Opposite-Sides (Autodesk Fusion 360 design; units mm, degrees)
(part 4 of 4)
extrude "Extrude2" cut sketch "Underside M3 insert" along normal blind 6.9
work_plane "WorkPlane3" AlongDistance 2.9 ExtraOffset 0
sketch "Underside M3 insert (1)" plane through (0, 0, 2.9) normal (0, 0, 1) x axis (1, 0, 0)
  circle C1 centre (-29, -55) radius 2
extrude "Extrude3" cut sketch "Underside M3 insert (1)" along normal blind 6.9
work_plane "WorkPlane4" AlongDistance 2.9 ExtraOffset 0
sketch "Underside M3 insert (2)" plane through (0, 0, 2.9) normal (0, 0, 1) x axis (1, 0, 0)
  circle C1 centre (-37, -55) radius 2
extrude "Extrude4" cut sketch "Underside M3 insert (2)" along normal blind 6.9
work_plane "WorkPlane5" AlongDistance 9.7 ExtraOffset 0
sketch "Preload screw passage" plane through (0, 0, 9.7) normal (0, 0, 1) x axis (1, 0, 0)
  circle C1 centre (-37, -55) radius 1.7
extrude "Extrude5" cut sketch "Preload screw passage" along normal blind 14.4
work_plane "WorkPlane6" AlongDistance 20 ExtraOffset 0
sketch "Preload collar recess" plane through (0, 0, 20) normal (0, 0, 1) x axis (1, 0, 0)
  circle C1 centre (-37, -55) radius 3.4
extrude "Extrude6" cut sketch "Preload collar recess" along normal blind 4.1
work_plane "WorkPlane7" AlongDistance -32.5 ExtraOffset 0
sketch "Spring mount insert and tip relief" plane through (-32.5, 0, 0) normal (1, 0, 0) x axis (0, 0, -1)
  circle C1 centre (-14, -62) radius 2
extrude "Extrude7" cut sketch "Spring mount insert and tip relief" along normal blind 8.6
work_plane "WorkPlane8" AlongDistance -32.5 ExtraOffset 0
sketch "Mount bore print-down crown" plane through (-32.5, 0, 0) normal (1, 0, 0) x axis (0, 0, -1)
  line L1 (-12.5858, -60.5858) -> (-12.5858, -63.4142)
  line L2 (-11.1716, -62) -> (-12.5858, -60.5858)
  line L3 (-12.5858, -63.4142) -> (-11.1716, -62)
extrude "Extrude8" cut sketch "Mount bore print-down crown" along normal blind 8.6
work_plane "WorkPlane1" AlongDistance -32 ExtraOffset 0
sketch "Spring block M3x20 -62" plane through (-32, 0, 0) normal (1, 0, 0) x axis (0, 0, -1)
  circle C1 centre (-14, -62) radius 1.5
extrude "Extrude1" new body sketch "Spring block M3x20 -62" along normal blind 20 bodies "HARDWARE Spring block M3x20 -62"
work_plane "WorkPlane2" AlongDistance -12 ExtraOffset 0
sketch "Button head" plane through (-12, 0, 0) normal (1, 0, 0) x axis (0, 0, -1)
  circle C1 centre (-14, -62) radius 2.75
extrude "Extrude2" add sketch "Button head" along normal blind 3
work_plane "WorkPlane9" AlongDistance -32.5 ExtraOffset 0
sketch "Spring mount insert and tip relief (1)" plane through (-32.5, 0, 0) normal (1, 0, 0) x axis (0, 0, -1)
  circle C1 centre (-14, -54) radius 2
extrude "Extrude9" cut sketch "Spring mount insert and tip relief (1)" along normal blind 8.6
work_plane "WorkPlane10" AlongDistance -32.5 ExtraOffset 0
sketch "Mount bore print-down crown (1)" plane through (-32.5, 0, 0) normal (1, 0, 0) x axis (0, 0, -1)
  line L1 (-12.5858, -52.5858) -> (-12.5858, -55.4142)
  line L2 (-11.1716, -54) -> (-12.5858, -52.5858)
  line L3 (-12.5858, -55.4142) -> (-11.1716, -54)
extrude "Extrude10" cut sketch "Mount bore print-down crown (1)" along normal blind 8.6
work_plane "WorkPlane1" AlongDistance -32 ExtraOffset 0
sketch "Spring block M3x20 -54" plane through (-32, 0, 0) normal (1, 0, 0) x axis (0, 0, -1)
  circle C1 centre (-14, -54) radius 1.5
extrude "Extrude1" new body sketch "Spring block M3x20 -54" along normal blind 20 bodies "HARDWARE Spring block M3x20 -54"
work_plane "WorkPlane2" AlongDistance -12 ExtraOffset 0
sketch "Button head" plane through (-12, 0, 0) normal (1, 0, 0) x axis (0, 0, -1)
  circle C1 centre (-14, -54) radius 2.75
extrude "Extrude2" add sketch "Button head" along normal blind 3
work_plane "WorkPlane24" AlongDistance 3.9 ExtraOffset 0
sketch "Retained service screw insert and tip relief" plane through (3.9, 0, 0) normal (1, 0, 0) x axis (0, 0, -1)
  circle C1 centre (-12, -55) radius 2
extrude "Extrude24" cut sketch "Retained service screw insert and tip relief" along normal blind 8.6
work_plane "WorkPlane25" AlongDistance 3.9 ExtraOffset 0
sketch "Service insert printable crown" plane through (3.9, 0, 0) normal (1, 0, 0) x axis (0, 0, -1)
  line L1 (-13.4142, -53.5858) -> (-13.4142, -56.4142)
  line L2 (-14.8284, -55) -> (-13.4142, -53.5858)
  line L3 (-13.4142, -56.4142) -> (-14.8284, -55)
extrude "Extrude25" cut sketch "Service insert printable crown" along normal blind 8.6
work_plane "WorkPlane1" AlongDistance 22 ExtraOffset 0
sketch "Narrow lower sensor panel" plane through (22, 0, 0) normal (1, 0, 0) x axis (0, 0, -1)
  line L1 (2.8307, 23.6631) -> (3.3, 23.7)
  line L2 (2.3729, 23.5532) -> (2.8307, 23.6631)
  line L3 (1.938, 23.373) -> (2.3729, 23.5532)
  line L4 (1.5366, 23.1271) -> (1.938, 23.373)
  line L5 (1.1787, 22.8213) -> (1.5366, 23.1271)
  line L6 (0.8729, 22.4634) -> (1.1787, 22.8213)
  line L7 (0.627, 22.062) -> (0.8729, 22.4634)
  line L8 (0.4468, 21.6271) -> (0.627, 22.062)
  line L9 (0.3369, 21.1693) -> (0.4468, 21.6271)
  line L10 (0.3, 20.7) -> (0.3369, 21.1693)
  line L11 (0.3, -20.7) -> (0.3, 20.7)
  line L12 (0.3369, -21.1693) -> (0.3, -20.7)
  line L13 (0.4468, -21.6271) -> (0.3369, -21.1693)
  line L14 (0.627, -22.062) -> (0.4468, -21.6271)
  line L15 (0.8729, -22.4634) -> (0.627, -22.062)
  line L16 (1.1787, -22.8213) -> (0.8729, -22.4634)
  line L17 (1.5366, -23.1271) -> (1.1787, -22.8213)
  line L18 (1.938, -23.373) -> (1.5366, -23.1271)
  line L19 (2.3729, -23.5532) -> (1.938, -23.373)
  line L20 (2.8307, -23.6631) -> (2.3729, -23.5532)
  line L21 (3.3, -23.7) -> (2.8307, -23.6631)
  line L22 (26.7, -23.7) -> (3.3, -23.7)
  line L23 (27.1693, -23.6631) -> (26.7, -23.7)
  line L24 (27.6271, -23.5532) -> (27.1693, -23.6631)
  line L25 (28.062, -23.373) -> (27.6271, -23.5532)
  line L26 (28.4634, -23.1271) -> (28.062, -23.373)
  line L27 (28.8213, -22.8213) -> (28.4634, -23.1271)
  line L28 (29.1271, -22.4634) -> (28.8213, -22.8213)
  line L29 (29.373, -22.062) -> (29.1271, -22.4634)
  line L30 (29.5532, -21.6271) -> (29.373, -22.062)
  line L31 (29.6631, -21.1693) -> (29.5532, -21.6271)
  line L32 (29.7, -20.7) -> (29.6631, -21.1693)
  line L33 (29.7, 20.7) -> (29.7, -20.7)
  line L34 (29.6631, 21.1693) -> (29.7, 20.7)
  line L35 (29.5532, 21.6271) -> (29.6631, 21.1693)
  line L36 (29.373, 22.062) -> (29.5532, 21.6271)
  line L37 (29.1271, 22.4634) -> (29.373, 22.062)
  line L38 (28.8213, 22.8213) -> (29.1271, 22.4634)
  line L39 (28.4634, 23.1271) -> (28.8213, 22.8213)
  line L40 (28.062, 23.373) -> (28.4634, 23.1271)
  line L41 (27.6271, 23.5532) -> (28.062, 23.373)
  line L42 (27.1693, 23.6631) -> (27.6271, 23.5532)
  line L43 (26.7, 23.7) -> (27.1693, 23.6631)
  line L44 (3.3, 23.7) -> (26.7, 23.7)
extrude "Extrude1" new body sketch "Narrow lower sensor panel" along normal blind 3 bodies "G03S Compact adjustable pot panel"
work_plane "WorkPlane2" AlongDistance 21.9 ExtraOffset 0
sketch "Measured pot bushing clearance" plane through (21.9, 0, 0) normal (1, 0, 0) x axis (0, 0, -1)
  circle C1 centre (15.15, 0) radius 3.6
extrude "Extrude2" cut sketch "Measured pot bushing clearance" along normal blind 3.2
work_plane "WorkPlane3" AlongDistance 21.9 ExtraOffset 0
sketch "Controlled mesh adjustment slot" plane through (21.9, 0, 0) normal (1, 0, 0) x axis (0, 0, -1)
  line L1 (17, -14.3) -> (17, -17.7)
  line L2 (13.1, -14.3) -> (17, -14.3)
  line L3 (13.1, -17.7) -> (13.1, -14.3)
  line L4 (17, -17.7) -> (13.1, -17.7)
extrude "Extrude3" cut sketch "Controlled mesh adjustment slot" along normal blind 3.2
work_plane "WorkPlane1" AlongDistance 13 ExtraOffset 0
sketch "Pot panel M3x12 -16" plane through (13, 0, 0) normal (1, 0, 0) x axis (0, 0, -1)
  circle C1 centre (15.15, -16) radius 1.5
extrude "Extrude1" new body sketch "Pot panel M3x12 -16" along normal blind 12 bodies "HARDWARE Pot panel M3x12 -16"
work_plane "WorkPlane2" AlongDistance 25 ExtraOffset 0
sketch "Button head" plane through (25, 0, 0) normal (1, 0, 0) x axis (0, 0, -1)
  circle C1 centre (15.15, -16) radius 2.75
extrude "Extrude2" add sketch "Button head" along normal blind 3
work_plane "WorkPlane4" AlongDistance 21.9 ExtraOffset 0
sketch "Controlled mesh adjustment slot (1)" plane through (21.9, 0, 0) normal (1, 0, 0) x axis (0, 0, -1)
  line L1 (17, 17.7) -> (17, 14.3)
  line L2 (13.1, 17.7) -> (17, 17.7)
  line L3 (13.1, 14.3) -> (13.1, 17.7)
  line L4 (17, 14.3) -> (13.1, 14.3)
extrude "Extrude4" cut sketch "Controlled mesh adjustment slot (1)" along normal blind 3.2
work_plane "WorkPlane1" AlongDistance 13 ExtraOffset 0
sketch "Pot panel M3x12 16" plane through (13, 0, 0) normal (1, 0, 0) x axis (0, 0, -1)
  circle C1 centre (15.15, 16) radius 1.5
extrude "Extrude1" new body sketch "Pot panel M3x12 16" along normal blind 12 bodies "HARDWARE Pot panel M3x12 16"
work_plane "WorkPlane2" AlongDistance 25 ExtraOffset 0
sketch "Button head" plane through (25, 0, 0) normal (1, 0, 0) x axis (0, 0, -1)
  circle C1 centre (15.15, 16) radius 2.75
extrude "Extrude2" add sketch "Button head" along normal blind 3
position "Position8"
work_plane "WorkPlane8" AlongDistance -45.2 ExtraOffset 0
sketch "Integral compression post removes loose spacer" plane through (-45.2, 0, 0) normal (1, 0, 0) x axis (0, 0, -1)
  circle C1 centre (39, -55) radius 6
extrude "Extrude8" add sketch "Integral compression post removes loose spacer" along normal blind 11.7
work_plane "WorkPlane9" AlongDistance -45.3 ExtraOffset 0
sketch "Continuous cassette screw bore" plane through (-45.3, 0, 0) normal (1, 0, 0) x axis (0, 0, -1)
  circle C1 centre (39, -55) radius 1.7
extrude "Extrude9" cut sketch "Continuous cassette screw bore" along normal blind 11.9
work_plane "WorkPlane10" AlongDistance -45.2 ExtraOffset 0
sketch "Integral compression post removes loose spacer (1)" plane through (-45.2, 0, 0) normal (1, 0, 0) x axis (0, 0, -1)
  circle C1 centre (39, -15) radius 6
extrude "Extrude10" add sketch "Integral compression post removes loose spacer (1)" along normal blind 11.7
work_plane "WorkPlane11" AlongDistance -45.3 ExtraOffset 0
sketch "Continuous cassette screw bore (1)" plane through (-45.3, 0, 0) normal (1, 0, 0) x axis (0, 0, -1)
  circle C1 centre (39, -15) radius 1.7
extrude "Extrude11" cut sketch "Continuous cassette screw bore (1)" along normal blind 11.9
work_plane "WorkPlane5" AlongDistance 21.9 ExtraOffset 0
sketch "Panel lower adjustment clearance" plane through (21.9, 0, 0) normal (1, 0, 0) x axis (0, 0, -1)
  line L1 (29.8, 24) -> (29.8, -24)
  line L2 (29.5, 24) -> (29.8, 24)
  line L3 (29.5, -24) -> (29.5, 24)
  line L4 (29.8, -24) -> (29.5, -24)
extrude "Extrude5" cut sketch "Panel lower adjustment clearance" along normal blind 3.2
work_plane "WorkPlane6" AlongDistance 21.9 ExtraOffset 0
sketch "Panel upper adjustment clearance" plane through (21.9, 0, 0) normal (1, 0, 0) x axis (0, 0, -1)
  line L1 (0.5, 24) -> (0.5, -24)
  line L2 (0.2, 24) -> (0.5, 24)
  line L3 (0.2, -24) -> (0.2, 24)
  line L4 (0.5, -24) -> (0.2, -24)
extrude "Extrude6" cut sketch "Panel upper adjustment clearance" along normal blind 3.2
work_plane "WorkPlane35" AlongDistance -24.1 ExtraOffset 0
sketch "Lower brace mounting clearance" plane through (-24.1, 0, 0) normal (1, 0, 0) x axis (0, 0, -1)
  circle C1 centre (-30, -60) radius 1.7
extrude "Extrude35" cut sketch "Lower brace mounting clearance" along normal blind 12.2
work_plane "WorkPlane36" AlongDistance -24.1 ExtraOffset 0
sketch "Lower brace mounting clearance (1)" plane through (-24.1, 0, 0) normal (1, 0, 0) x axis (0, 0, -1)
  circle C1 centre (-40, -60) radius 1.7
extrude "Extrude36" cut sketch "Lower brace mounting clearance (1)" along normal blind 12.2
work_plane "WorkPlane37" AlongDistance -24.1 ExtraOffset 0
sketch "Lower brace mounting clearance (2)" plane through (-24.1, 0, 0) normal (1, 0, 0) x axis (0, 0, -1)
  circle C1 centre (-30, 60) radius 1.7
extrude "Extrude37" cut sketch "Lower brace mounting clearance (2)" along normal blind 12.2
work_plane "WorkPlane38" AlongDistance -24.1 ExtraOffset 0
sketch "Lower brace mounting clearance (3)" plane through (-24.1, 0, 0) normal (1, 0, 0) x axis (0, 0, -1)
  circle C1 centre (-40, 60) radius 1.7
extrude "Extrude38" cut sketch "Lower brace mounting clearance (3)" along normal blind 12.2
work_plane "WorkPlane19" AlongDistance 11.9 ExtraOffset 0
sketch "Lower brace mounting clearance" plane through (11.9, 0, 0) normal (1, 0, 0) x axis (0, 0, -1)
  circle C1 centre (-30, -60) radius 1.7
extrude "Extrude19" cut sketch "Lower brace mounting clearance" along normal blind 12.2
work_plane "WorkPlane20" AlongDistance 11.9 ExtraOffset 0
sketch "Lower brace mounting clearance (1)" plane through (11.9, 0, 0) normal (1, 0, 0) x axis (0, 0, -1)
  circle C1 centre (-40, -60) radius 1.7
extrude "Extrude20" cut sketch "Lower brace mounting clearance (1)" along normal blind 12.2
work_plane "WorkPlane21" AlongDistance 11.9 ExtraOffset 0
sketch "Lower brace mounting clearance (2)" plane through (11.9, 0, 0) normal (1, 0, 0) x axis (0, 0, -1)
  circle C1 centre (-30, 60) radius 1.7
extrude "Extrude21" cut sketch "Lower brace mounting clearance (2)" along normal blind 12.2
work_plane "WorkPlane22" AlongDistance 11.9 ExtraOffset 0
sketch "Lower brace mounting clearance (3)" plane through (11.9, 0, 0) normal (1, 0, 0) x axis (0, 0, -1)
  circle C1 centre (-40, 60) radius 1.7
extrude "Extrude22" cut sketch "Lower brace mounting clearance (3)" along normal blind 12.2
position "Position9"
mirror "Mirror1" mirrorStitchTolerance 0.01 bodies "P08 Cam 8 gates - 116 degree span"
remove_body "RemoveBody1"
mirror "Mirror1" mirrorStitchTolerance 0.01 bodies "P08 Cam 7 gates - 116 degree span"
remove_body "RemoveBody1"
mirror "Mirror1" mirrorStitchTolerance 0.01 bodies "P08 Cam 5 gates - 116 degree span"
remove_body "RemoveBody1"
mirror "Mirror1" mirrorStitchTolerance 0.01 bodies "P08 Cam 3 gates - 116 degree span"
remove_body "RemoveBody1"
position "Position10"
work_plane "WorkPlane4" AlongDistance -37.3 ExtraOffset 0
sketch "One mm flange provides carrier clearance without underside pocket" plane through (-37.3, 0, 0) normal (1, 0, 0) x axis (0, 0, -1)
  line L1 (-52, 13) -> (-52, -13)
  line L2 (-78, 13) -> (-52, 13)
  line L3 (-78, -13) -> (-78, 13)
  line L4 (-52, -13) -> (-78, -13)
extrude "Extrude4" cut sketch "One mm flange provides carrier clearance without underside pocket" along normal blind 0.3
work_plane "WorkPlane13" AlongDistance -28 ExtraOffset 0
sketch "Carry clamp boss footprint directly to print bed" plane through (-28, 0, 0) normal (1, 0, 0) x axis (0, 0, -1)
  line L1 (-25, 14.8) -> (-25, 11.5)
  line L2 (-35, 14.8) -> (-25, 14.8)
  line L3 (-35, 11.5) -> (-35, 14.8)
  line L4 (-25, 11.5) -> (-35, 11.5)
extrude "Extrude13" add sketch "Carry clamp boss footprint directly to print bed" along normal blind 2.5
work_plane "WorkPlane15" AlongDistance -7 ExtraOffset 0
sketch "Carry rotor clamp seat directly to print bed" plane through (-7, 0, 0) normal (1, 0, 0) x axis (0, 0, -1)
  line L1 (-25, 22.5) -> (-25, 21.4)
  line L2 (-35, 22.5) -> (-25, 22.5)
  line L3 (-35, 21.4) -> (-35, 22.5)
  line L4 (-25, 21.4) -> (-35, 21.4)
extrude "Extrude15" add sketch "Carry rotor clamp seat directly to print bed" along normal blind 2
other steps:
create_component "CreateComponent1"
create_component "CreateComponent4"
create_component "CreateComponent5"
create_component "CreateComponent12"
create_component "CreateComponent13"
create_component "CreateComponent14"
create_component "CreateComponent49"
create_component "CreateComponent146"
create_component "CreateComponent147"
create_component "CreateComponent152"
create_component "CreateComponent153"
create_component "CreateComponent154"
create_component "CreateComponent155"
create_component "CreateComponent156"
create_component "CreateComponent157"
create_component "CreateComponent158"
create_component "CreateComponent159"
create_component "CreateComponent160"
create_component "CreateComponent161"
create_component "CreateComponent176"
create_component "CreateComponent177"
create_component "CreateComponent178"
create_component "CreateComponent179"
create_component "CreateComponent186"
create_component "CreateComponent188"
create_component "CreateComponent194"
create_component "CreateComponent195"
create_component "CreateComponent196"
create_component "CreateComponent201"
create_component "CreateComponent215"
create_component "CreateComponent216"
create_component "CreateComponent217"
create_component "CreateComponent218"
create_component "CreateComponent219"
create_component "CreateComponent220"
create_component "CreateComponent221"
create_component "CreateComponent222"
create_component "CreateComponent223"
create_component "CreateComponent224"
create_component "CreateComponent225"
create_component "CreateComponent226"
create_component "CreateComponent227"
create_component "CreateComponent228"
create_component "CreateComponent229"
create_component "CreateComponent230"
create_component "CreateComponent231"
create_component "CreateComponent232"
create_component "CreateComponent233"
create_component "CreateComponent234"
create_component "CreateComponent235"
create_component "CreateComponent236"
create_component "CreateComponent238"
create_component "CreateComponent240"
create_component "CreateComponent241"
create_component "CreateComponent242"
create_component "CreateComponent243"
create_component "CreateComponent244"
create_component "CreateComponent245"
create_component "CreateComponent246"
create_component "CreateComponent247"
create_component "CreateComponent248"
create_component "CreateComponent249"
create_component "CreateComponent250"
create_component "CreateComponent251"
create_component "CreateComponent252"
create_component "CreateComponent253"
create_component "CreateComponent254"
create_component "CreateComponent255"
create_component "CreateComponent257"
create_component "CreateComponent259"
create_component "CreateComponent260"
create_component "CreateComponent261"
create_component "CreateComponent262"
create_component "CreateComponent263"
create_component "CreateComponent264"
create_component "CreateComponent265"
create_component "CreateComponent266"
create_component "CreateComponent267"
named bodies: "P03 Left flanged journal bush", "P04 Right flanged journal bush", "P09 Grip insert half", "P10 Grip screw half", "P11 Forked roller follower", "HARDWARE Roller axle M3 nut", "HARDWARE Grip M3x20 cap head 180", "HARDWARE Grip M3x20 cap head 190", "HARDWARE 623ZZ roller bearing at 8", "HARDWARE 623ZZ roller bearing at 12", "P27 Printed guide sleeve 4", "HARDWARE Cup guide M3x12 4", "P27 Printed guide sleeve 20", "HARDWARE Cup guide M3x12 20", "P14 Captive spring cup for 9 mm spring", "P15 Recessed preload limit collar 1 mm", "HARDWARE Preload M3x20 cap head", "REFERENCE Stock spring OD9 wire1 free20 - rate and solid height assumed", "HARDWARE Cam M3x10 cap head -45", "HARDWARE Cam M3x10 cap head 0", "HARDWARE Cam M3x10 cap head 45", "HARDWARE Roller axle M3x20 cap head", "G01R 48T gear with upper clamp", "G02 24T sensor pinion", "HARDWARE Geared RK097 supplied washer ASSUMED", "HARDWARE Geared RK097 supplied nut ASSUMED", "HARDWARE G02 24T sensor pinion clamp M3x12", "HARDWARE G01 upper clamp M3x12", "P08 Cam 8 gates - 116 degree span", "P08 Cam 7 gates - 116 degree span", "P08 Cam 5 gates - 116 degree span", "P08 Cam 3 gates - 116 degree span", "REFERENCE Geared pot user measured 2026-10-25", "P01S Continuous left structural plate", "HARDWARE Top rail M5x14 (-1, -1)", "HARDWARE Top rail M5x14 (-1, 1)", "P02S Continuous right sensor plate", "HARDWARE Top rail M5x14 (1, -1)", "HARDWARE Top rail M5x14 (1, 1)", "P30 Crossbrace -60", "HARDWARE Brace M3x20 (-60, -1, 35)", "HARDWARE Brace M3x20 (-60, -1, 45)", "HARDWARE Brace M3x20 (-60, 1, 35)", "HARDWARE Brace M3x20 (-60, 1, 45)", "P30 Crossbrace 60", "HARDWARE Brace M3x20 (60, -1, 35)", "HARDWARE Brace M3x20 (60, -1, 45)", "HARDWARE Brace M3x20 (60, 1, 35)", "HARDWARE Brace M3x20 (60, 1, 45)", "P31 Positively located stop -1", "P31 Positively located stop 1", "P05S Shaft lower half", "HARDWARE Shaft joining M3x8 -8", "HARDWARE Shaft joining M3x8 8", "P05S Shaft upper half", "P28 Shaft alignment key", "P06 Shaft retaining cap", "HARDWARE Main shaft cap M3x8", "P07S Planar lever rotor with lower stop lug", "HARDWARE Rotor clamp M3x16"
